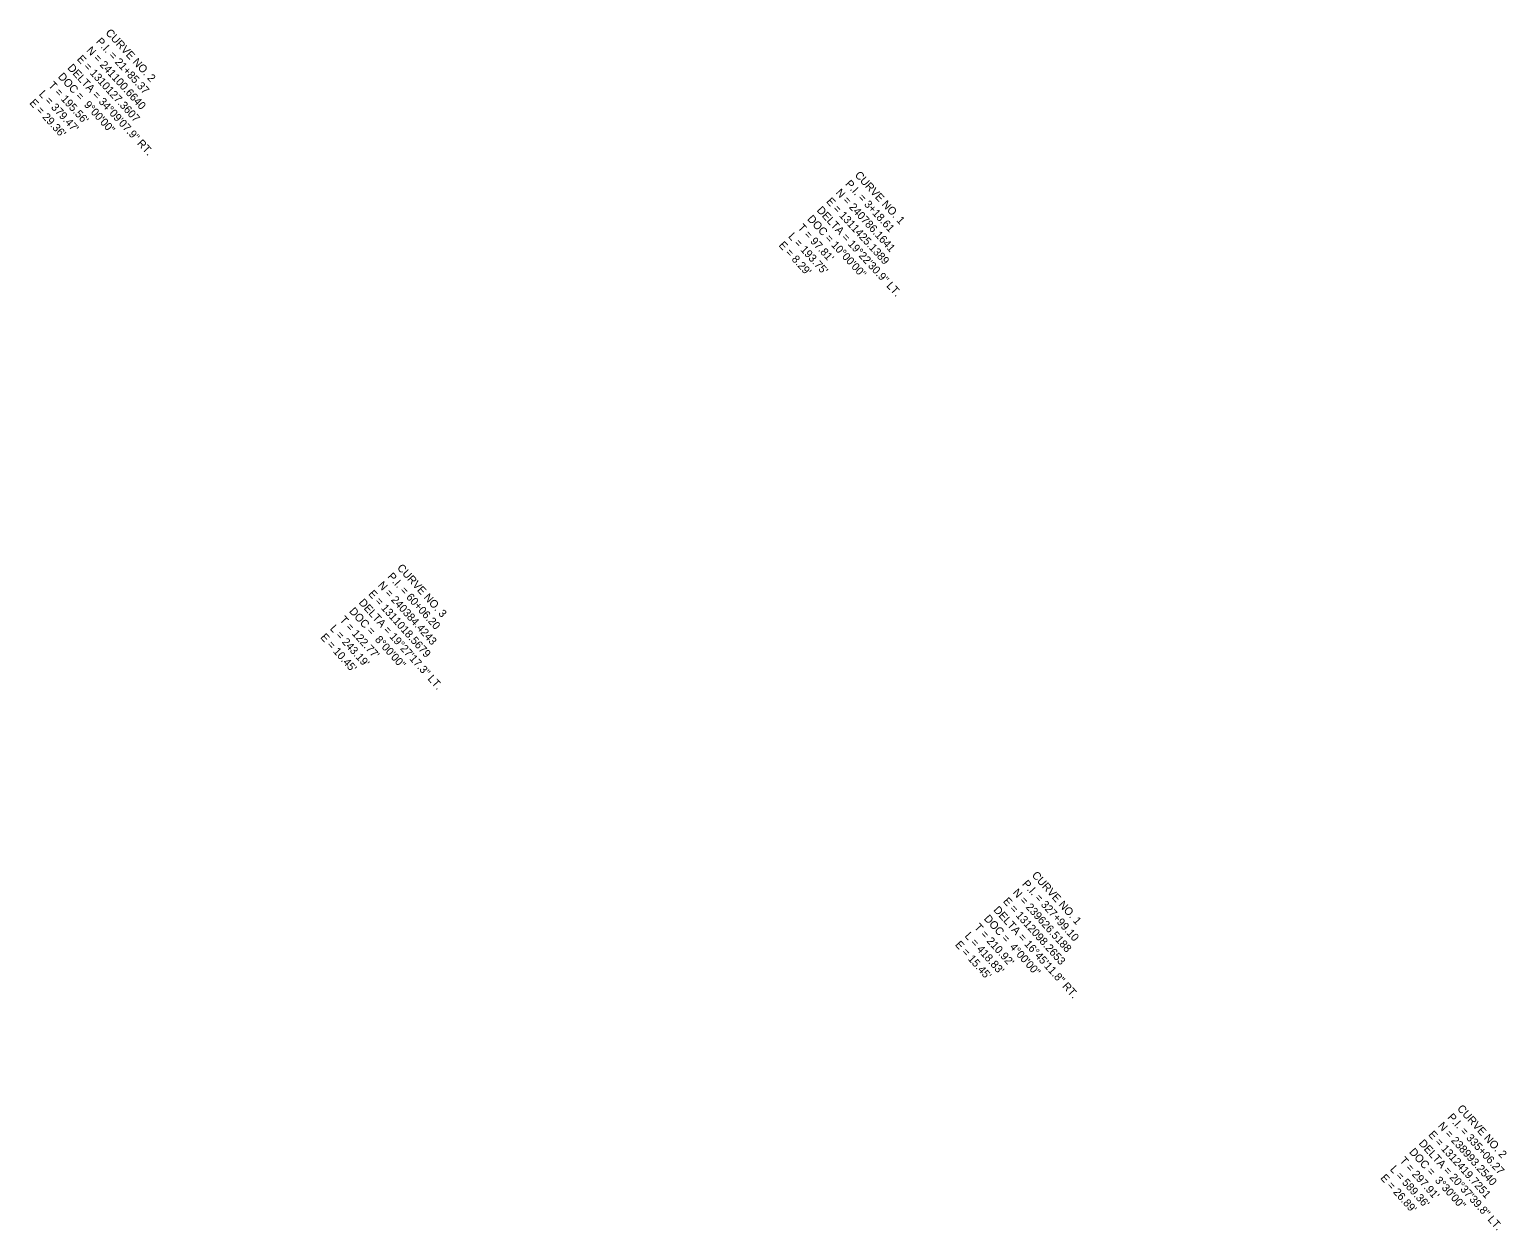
# Model space of a CAD drawing. Extents: x 1300404 to 1323571, y 234004 to 252077.
# Drawn here: x 1314731 to 1317358, y 234004 to 236139 of the extents above; entities that cross this region are included whole.
import ezdxf

# ---------------------------------------------------------------- set-up
doc = ezdxf.new("R2010")
doc.units = 0
doc.layers.add('R_Curve Data OLD', color=7, linetype='Continuous')

msp = doc.modelspace()

# ---------------------------------------------------------------- texts
at = {"layer": 'R_Curve Data OLD'}
for s, rotation, p in [('CURVE NO. 2', 312.6792, (1314865.7, 236132)), ('N = 241100.6640', 312.6792, (1314831.8, 236100.8)), ('P.I. = 21+85.37', 312.6792, (1314848.8, 236116.4)), ('E = 1310127.3607', 312.6792, (1314814.9, 236085.3)), ('DOC =  9%%d00\'00"', 312.6792, (1314781.1, 236054.1)), ('DELTA = 34%%d09\'07.9" RT.', 312.6792, (1314798, 236069.7)), ("L = 379.47'", 312.6792, (1314747.3, 236022.9)), ("T = 195.56'", 312.6792, (1314764.2, 236038.5)), ("E = 29.36'", 312.6792, (1314730.4, 236007.3)), ('CURVE NO. 1', 312.6814, (1316198.2, 235879)), ('N = 240786.1641', 312.6814, (1316164.4, 235847.8)), ('P.I. = 3+18.61', 312.6814, (1316181.3, 235863.4)), ('DELTA = 19%%d22\'30.9" LT.', 312.6814, (1316130.6, 235816.6)), ('E = 1311425.1389', 312.6814, (1316147.5, 235832.2)), ("T = 97.81'", 312.6814, (1316096.8, 235785.5)), ('DOC = 10%%d00\'00"', 312.6814, (1316113.7, 235801)), ("L = 193.75'", 312.6814, (1316079.9, 235769.9)), ("E = 8.29'", 312.6814, (1316062.9, 235754.3)), ('P.I. = 60+06.20', 312.132, (1315367.2, 235165.4)), ('CURVE NO. 3', 312.132, (1315384.2, 235180.8)), ('E = 1311018.5679', 312.132, (1315333.1, 235134.5)), ('N = 240384.4243', 312.132, (1315350.1, 235149.9)), ('DOC =  8%%d00\'00"', 312.132, (1315299, 235103.7)), ('DELTA = 19%%d27\'17.3" LT.', 312.132, (1315316, 235119.1)), ("T = 122.77'", 312.132, (1315281.9, 235088.2)), ("E = 10.45'", 312.132, (1315247.8, 235057.4)), ("L = 243.19'", 312.132, (1315264.8, 235072.8)), ('CURVE NO. 1', 312.132, (1316513.1, 234634.4)), ('N = 239626.5188', 312.132, (1316479, 234603.5)), ('P.I. = 327+99.10', 312.132, (1316496, 234618.9)), ('E = 1312098.2653', 312.132, (1316461.9, 234588.1)), ('DOC =  4%%d00\'00"', 312.132, (1316427.8, 234557.2)), ('DELTA = 16%%d45\'11.8" RT.', 312.132, (1316444.8, 234572.6)), ("L = 418.83'", 312.132, (1316393.7, 234526.4)), ("T = 210.92'", 312.132, (1316410.7, 234541.8)), ("E = 15.45'", 312.132, (1316376.6, 234510.9)), ('CURVE NO. 2', 312.132, (1317269.5, 234219.5)), ('N = 238993.2540', 312.132, (1317235.3, 234188.7)), ('P.I. = 335+06.27', 312.132, (1317252.4, 234204.1)), ('DELTA = 20%%d37\'39.8" LT.', 312.132, (1317201.2, 234157.8)), ('E = 1312419.7251', 312.132, (1317218.3, 234173.2)), ('DOC =  3%%d30\'00"', 312.132, (1317184.2, 234142.4)), ("L = 589.36'", 312.132, (1317150.1, 234111.5)), ("T = 297.91'", 312.132, (1317167.1, 234126.9)), ("E = 26.89'", 312.132, (1317133, 234096.1))]:
    msp.add_text(s, height=14, rotation=rotation, dxfattribs=at).set_placement(p)

doc.saveas('drawing.dxf')
